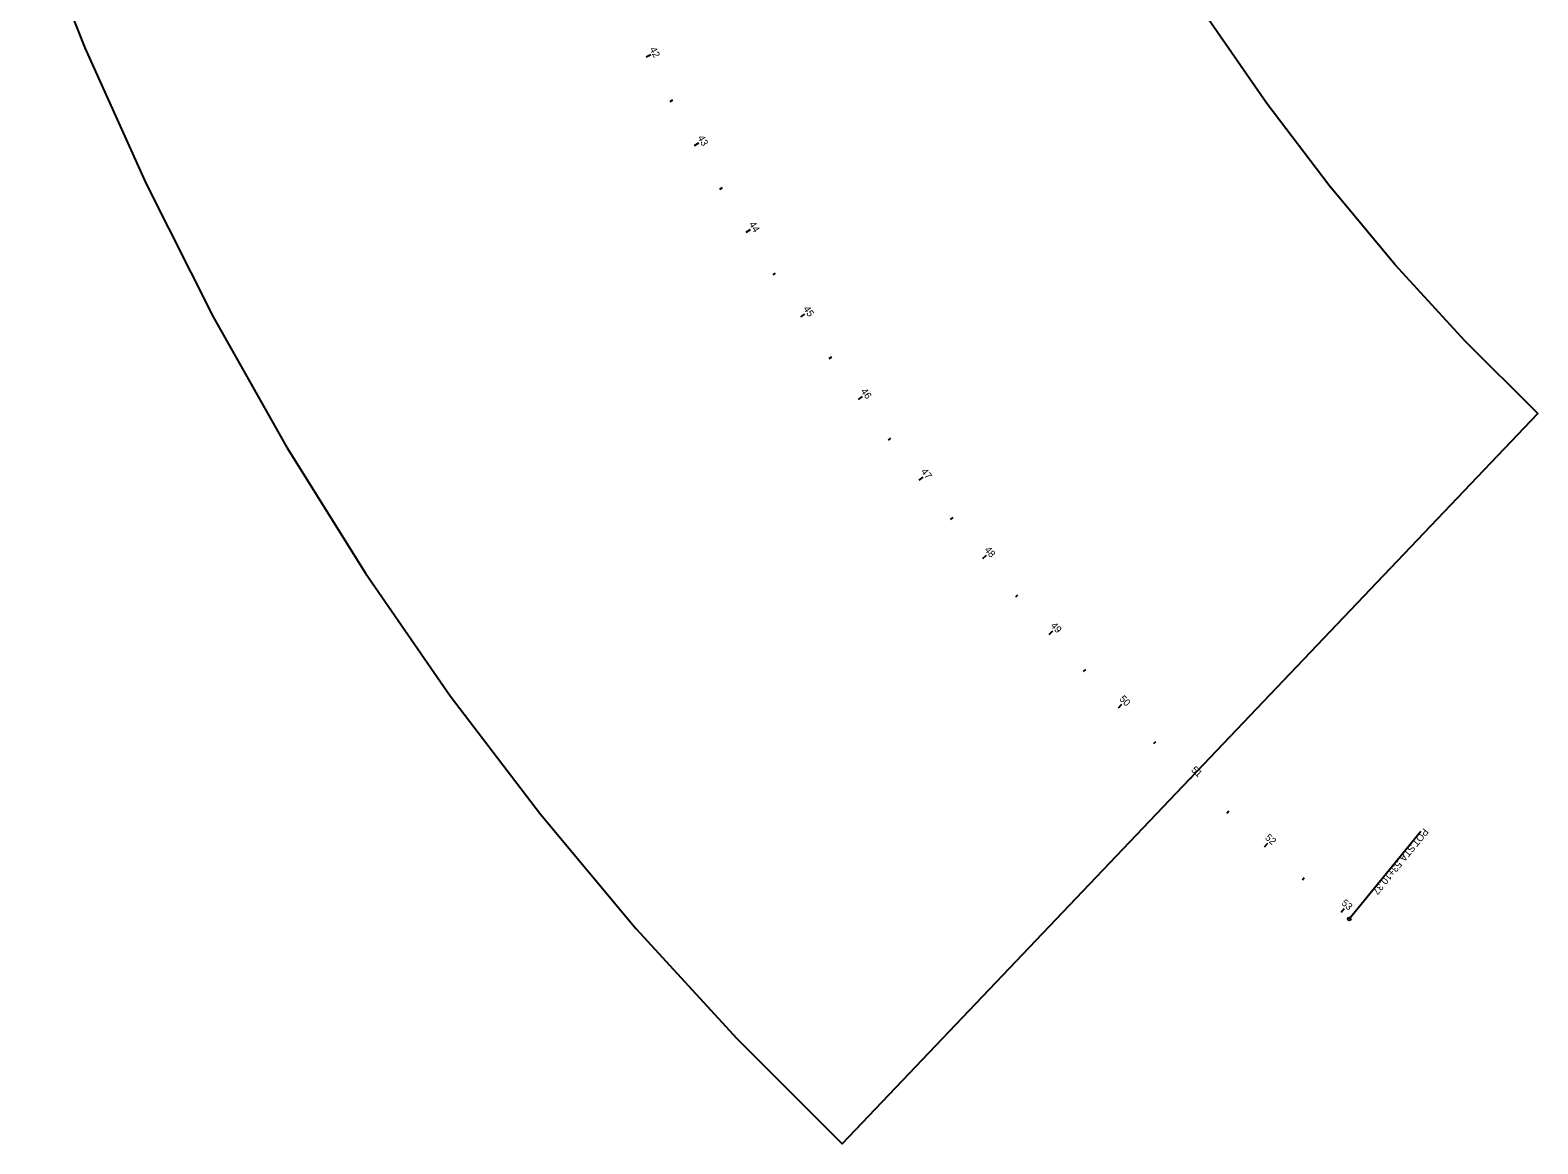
# Model space of a CAD drawing. Extents: x 75725 to 90554, y 518585 to 527848.
# Drawn here: x 87430 to 88925, y 518585 to 519689 of the extents above; entities that cross this region are included whole.
import ezdxf

# ---------------------------------------------------------------- set-up
doc = ezdxf.new("R2010")
doc.units = 0
for name, color, linetype in [('GE_P_Alignment_100_Cardinal_Points', 7, 'Continuous'), ('GE_P_Alignment_100_Stations', 7, 'Continuous'), ('SH_Named_Boundary', 7, 'Continuous')]:
    doc.layers.add(name, color=color, linetype=linetype)

msp = doc.modelspace()

# ---------------------------------------------------------------- linework, layer by layer
at = {"layer": 'GE_P_Alignment_100_Cardinal_Points'}
msp.add_line((88737.9, 518808.1), (88809, 518895.3), dxfattribs=at)
msp.add_circle((88737.9, 518808.1), 1.5, dxfattribs=at)
at = {"layer": 'GE_P_Alignment_100_Stations'}
for p, q in [((88040.9, 519662.8), (88045.4, 519665.1)), ((88064.5, 519618.7), (88067.1, 519620.1)), ((88088.9, 519575.1), (88093.2, 519577.5)), ((88114, 519531.8), (88116.6, 519533.4)), ((88140, 519489.1), (88144.2, 519491.7)), ((88166.7, 519446.8), (88169.2, 519448.5)), ((88194.2, 519405.1), (88198.3, 519407.8)), ((88222.4, 519363.8), (88224.9, 519365.5)), ((88251.4, 519323.1), (88255.4, 519326)), ((88281.1, 519282.9), (88283.5, 519284.7)), ((88311.6, 519243.2), (88315.5, 519246.3)), ((88342.7, 519204.1), (88345.1, 519206)), ((88374.6, 519165.6), (88378.4, 519168.8)), ((88407.2, 519127.6), (88409.4, 519129.6)), ((88440.4, 519090.3), (88444.1, 519093.7)), ((88474.4, 519053.6), (88476.6, 519055.6)), ((88509, 519017.5), (88512.5, 519021)), ((88544.2, 518982), (88546.3, 518984.2)), ((88580.1, 518947.2), (88583.6, 518950.8)), ((88616.6, 518913.1), (88618.7, 518915.3)), ((88653.8, 518879.6), (88657.1, 518883.3)), ((88691.5, 518846.8), (88693.4, 518849.1)), ((88729.8, 518814.7), (88733, 518818.5))]:
    msp.add_line(p, q, dxfattribs=at)
at = {"layer": 'SH_Named_Boundary'}
msp.add_lwpolyline([(88368, 520155.8), (87430, 519809.1), (87484.4, 519671.7), (87545, 519536.9), (87611.6, 519405), (87684.2, 519276.3), (87762.6, 519151.1), (87846.6, 519029.5), (87936.1, 518911.9), (88030.8, 518798.5), (88130.6, 518689.5), (88235.3, 518585.2), (88924.9, 519309.3), (88852.6, 519381.4), (88783.5, 519456.8), (88718, 519535.3), (88656.1, 519616.6), (88598, 519700.7), (88543.8, 519787.3), (88493.6, 519876.4), (88447.5, 519967.6), (88405.6, 520060.8)], close=True, dxfattribs=at)

# ---------------------------------------------------------------- texts
at = {"layer": 'GE_P_Alignment_100_Cardinal_Points'}
for s, p in [('POT', (88811.8, 518898.6)), (' STA. ', (88800.4, 518884.7)), ('53+10.37', (88785.5, 518866.3))]:
    msp.add_text(s, height=7, rotation=230.7887, dxfattribs=at).set_placement(p)
at = {"layer": 'GE_P_Alignment_100_Stations'}
for s, rotation, p in [('42', 297.5979, (88044, 519670.5)), ('43', 299.6865, (88091.6, 519582.8)), ('44', 301.7751, (88142.5, 519497)), ('45', 303.8636, (88196.3, 519413.1)), ('46', 305.9522, (88253.2, 519331.3)), ('47', 308.0408, (88312.9, 519251.6)), ('48', 310.1293, (88375.8, 519173.8)), ('49', 312.2179, (88441.4, 519098.6)), ('50', 314.3065, (88509.5, 519025.8)), ('51', 316.395, (88580.7, 518955.3)), ('52', 318.4836, (88653.9, 518887.9)), ('53', 320.5721, (88729.6, 518822.9))]:
    msp.add_text(s, height=7, rotation=rotation, dxfattribs=at).set_placement(p)

doc.saveas('drawing.dxf')
